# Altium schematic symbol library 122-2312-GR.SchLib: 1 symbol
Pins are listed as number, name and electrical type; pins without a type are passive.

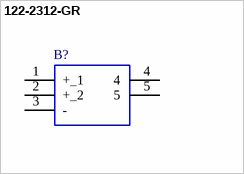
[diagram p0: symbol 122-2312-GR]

## 122-2312-GR
designator B?
Single Cell Holder; Manufacturer_Name: Eagle Plastic Devices; Geometry.Height: 5.4mm
footprint 1222312GR
pins: 1 +_1, 2 +_2, 3 -, 4, 5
